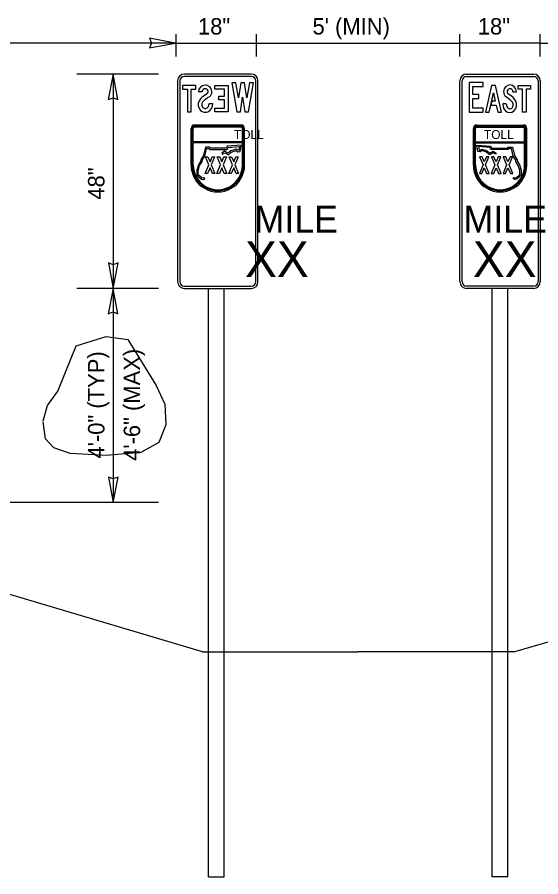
# Model space of a CAD drawing. Extents: x 56768 to 57406, y 11696 to 12105.
# Drawn here: x 56946.4 to 57035.7, y 11762.4 to 11908.9 of the extents above; entities that cross this region are included whole.
import ezdxf

# ---------------------------------------------------------------- set-up
doc = ezdxf.new("R2010")
doc.units = 0
for name, color, linetype in [('1', 7, 'Continuous'), ('52', 7, 'Continuous'), ('62', 7, 'Continuous'), ('DimLines_dp', 7, 'Continuous'), ('SignPanel', 7, 'Continuous'), ('XSGrdLine_ex', 7, 'Continuous')]:
    doc.layers.add(name, color=color, linetype=linetype)

msp = doc.modelspace()

# ---------------------------------------------------------------- linework, layer by layer
at = {"layer": '1'}
for p, q in [((56979.04, 11800.77), (56979.04, 11862.72)), ((56981.7, 11800.77), (56981.7, 11862.72)), ((57027.41, 11800.77), (57027.41, 11862.72)), ((57030.07, 11800.77), (57030.07, 11862.72)), ((56979.04, 11762.45), (56979.04, 11800.77)), ((56981.7, 11762.45), (56981.7, 11800.77)), ((57027.41, 11762.45), (57027.41, 11800.77)), ((57030.07, 11762.45), (57030.07, 11800.77)), ((56979.04, 11762.45), (56981.7, 11762.45)), ((57030.07, 11762.45), (57027.41, 11762.45))]:
    msp.add_line(p, q, dxfattribs=at)
at = {"layer": '52'}
msp.add_line((56970.53, 11826.22), (56892.41, 11826.22), dxfattribs=at)
at = {"layer": '62'}
msp.add_lwpolyline([(56950.87, 11840.16), (56951.57, 11842.76), (56953.37, 11845.17), (56956.48, 11852.92), (56961.58, 11854.52), (56965.28, 11854.02), (56970.08, 11846.17), (56971.58, 11842.96), (56971.78, 11839.46), (56970.58, 11836.46), (56967.48, 11834.75), (56961.58, 11834.25), (56955.47, 11834.55), (56952.67, 11835.56), (56951.27, 11837.06), (56950.87, 11839.96)], dxfattribs=at)
at = {"layer": 'DimLines_dp'}
for p, q in [((56973.53, 11902.22), (56973.53, 11906.05)), ((56987.21, 11902.22), (56987.21, 11906.05)), ((57021.89, 11902.22), (57021.89, 11906.05)), ((57035.58, 11902.22), (57035.58, 11906.05)), ((56973.53, 11904.5), (56892.41, 11904.5)), ((56973.34, 11904.5), (56968.99, 11905.34)), ((56968.99, 11905.34), (56969.32, 11904.5)), ((56969.32, 11904.5), (56968.99, 11903.69)), ((56968.99, 11903.69), (56973.34, 11904.5)), ((56973.53, 11904.5), (56987.21, 11904.5)), ((56987.21, 11904.5), (57021.89, 11904.5)), ((57035.58, 11904.5), (57021.89, 11904.5)), ((57035.58, 11904.5), (57116.7, 11904.5)), ((56970.53, 11899.22), (56956.6, 11899.22)), ((56962.78, 11899.22), (56961.94, 11894.87)), ((56962.78, 11899.22), (56962.78, 11862.72)), ((56963.59, 11894.87), (56962.78, 11899.22)), ((56961.94, 11894.87), (56962.78, 11895.2)), ((56962.78, 11895.2), (56963.59, 11894.87)), ((56962.78, 11866.74), (56961.97, 11867.07)), ((56961.97, 11867.07), (56962.78, 11862.72)), ((56962.78, 11866.74), (56961.97, 11867.07)), ((56961.97, 11867.07), (56962.78, 11862.72)), ((56962.78, 11862.72), (56963.62, 11867.07)), ((56963.62, 11867.07), (56962.78, 11866.74)), ((56962.78, 11862.72), (56963.62, 11867.07)), ((56963.62, 11867.07), (56962.78, 11866.74)), ((56970.53, 11862.72), (56956.6, 11862.72)), ((56962.78, 11862.72), (56961.94, 11858.37)), ((56962.78, 11862.72), (56962.78, 11826.22)), ((56963.59, 11858.37), (56962.78, 11862.72)), ((56961.94, 11858.37), (56962.78, 11858.7)), ((56962.78, 11858.7), (56963.59, 11858.37)), ((56962.78, 11830.24), (56961.97, 11830.57)), ((56961.97, 11830.57), (56962.78, 11826.22)), ((56962.78, 11826.22), (56963.62, 11830.57)), ((56963.62, 11830.57), (56962.78, 11830.24))]:
    msp.add_line(p, q, dxfattribs=at)
at = {"layer": 'SignPanel'}
for p, q in [((56977.92, 11896.21), (56977.31, 11896.21)), ((56977.92, 11896.21), (56977.31, 11896.21)), ((56977.92, 11896.21), (56977.31, 11896.21)), ((57030.93, 11896.21), (57031.52, 11896.21)), ((57030.93, 11896.21), (57031.52, 11896.21)), ((57030.93, 11896.21), (57031.52, 11896.21)), ((56979.12, 11894.2), (56979.74, 11894.2)), ((56979.12, 11894.2), (56979.74, 11894.2)), ((56979.12, 11894.2), (56979.74, 11894.2)), ((57029.79, 11894.17), (57029.2, 11894.17)), ((57029.79, 11894.17), (57029.2, 11894.17)), ((57029.79, 11894.17), (57029.2, 11894.17)), ((56976.05, 11883.7), (56976.05, 11889.98)), ((56976.25, 11883.7), (56976.25, 11889.98)), ((56976.44, 11887.7), (56976.44, 11889.98)), ((56984.61, 11890.55), (56976.62, 11890.55)), ((56984.61, 11890.36), (56976.62, 11890.36)), ((56984.61, 11890.17), (56976.62, 11890.17)), ((56984.8, 11887.7), (56984.8, 11889.98)), ((56984.99, 11883.7), (56984.99, 11889.98)), ((56985.18, 11883.7), (56985.18, 11889.98)), ((57024.18, 11883.7), (57024.18, 11889.98)), ((57024.37, 11883.7), (57024.37, 11889.98)), ((57024.55, 11887.7), (57024.55, 11889.98)), ((57024.75, 11890.55), (57032.73, 11890.55)), ((57024.75, 11890.36), (57032.73, 11890.36)), ((57024.75, 11890.17), (57032.73, 11890.17)), ((57032.92, 11887.7), (57032.92, 11889.98)), ((57033.11, 11883.7), (57033.11, 11889.98)), ((57033.3, 11883.7), (57033.3, 11889.98)), ((56984.8, 11887.7), (56976.44, 11887.7)), ((56976.44, 11883.7), (56976.44, 11887.51)), ((56984.8, 11887.51), (56976.44, 11887.51)), ((56978.5, 11886.77), (56978.17, 11885.34)), ((56979.24, 11886.77), (56978.5, 11886.77)), ((56979.34, 11886.62), (56979.24, 11886.77)), ((56982.07, 11886.62), (56979.34, 11886.62)), ((56982.21, 11886.96), (56982.07, 11886.62)), ((56984.59, 11887.14), (56982.21, 11886.96)), ((56982.23, 11886.39), (56982.37, 11886.74)), ((56982.37, 11886.74), (56984.31, 11886.89)), ((56983.33, 11886.8), (56983.33, 11886.8)), ((56984.31, 11886.89), (56984.22, 11886.26)), ((56984.42, 11886.05), (56984.59, 11887.14)), ((56984.8, 11883.7), (56984.8, 11887.51)), ((57024.55, 11887.7), (57032.92, 11887.7)), ((57024.55, 11883.7), (57024.55, 11887.51)), ((57024.55, 11887.51), (57032.92, 11887.51)), ((57024.94, 11886.05), (57024.77, 11887.14)), ((57024.77, 11887.14), (57027.15, 11886.96)), ((57026.99, 11886.74), (57025.04, 11886.89)), ((57025.04, 11886.89), (57025.14, 11886.26)), ((57026.03, 11886.8), (57026.03, 11886.8)), ((57027.13, 11886.39), (57026.99, 11886.74)), ((57027.15, 11886.96), (57027.28, 11886.62)), ((57027.28, 11886.62), (57030.01, 11886.62)), ((57030.01, 11886.62), (57030.12, 11886.77)), ((57030.12, 11886.77), (57030.85, 11886.77)), ((57030.85, 11886.77), (57031.18, 11885.34)), ((57032.92, 11883.7), (57032.92, 11887.51)), ((56978.17, 11885.34), (56977.72, 11884.61)), ((56977.95, 11884.54), (56978.39, 11885.25)), ((56978.39, 11885.25), (56978.69, 11886.54)), ((56978.69, 11886.54), (56979.12, 11886.54)), ((56979.12, 11886.54), (56979.22, 11886.39)), ((56979.22, 11886.39), (56982.23, 11886.39)), ((56981.78, 11886.09), (56981.28, 11885.75)), ((56981.28, 11885.75), (56981.41, 11885.56)), ((56981.41, 11885.56), (56981.79, 11885.82)), ((56982.39, 11885.73), (56981.78, 11886.09)), ((56981.79, 11885.82), (56982.42, 11885.45)), ((56982.84, 11886.15), (56982.39, 11885.73)), ((56982.42, 11885.45), (56982.96, 11885.95)), ((56983.76, 11886.45), (56982.84, 11886.15)), ((56982.96, 11885.95), (56983.71, 11886.19)), ((56983.71, 11886.19), (56983.96, 11886)), ((56984.03, 11886.24), (56983.76, 11886.45)), ((56983.96, 11886), (56984.42, 11886.05)), ((56984.22, 11886.26), (56984.03, 11886.24)), ((57025.39, 11886), (57024.94, 11886.05)), ((57025.14, 11886.26), (57025.33, 11886.24)), ((57025.33, 11886.24), (57025.6, 11886.45)), ((57025.64, 11886.19), (57025.39, 11886)), ((57025.6, 11886.45), (57026.52, 11886.15)), ((57026.4, 11885.95), (57025.64, 11886.19)), ((57026.94, 11885.45), (57026.4, 11885.95)), ((57026.52, 11886.15), (57026.97, 11885.73)), ((57027.57, 11885.82), (57026.94, 11885.45)), ((57026.97, 11885.73), (57027.58, 11886.09)), ((57030.14, 11886.39), (57027.13, 11886.39)), ((57027.95, 11885.56), (57027.57, 11885.82)), ((57027.58, 11886.09), (57028.08, 11885.75)), ((57028.08, 11885.75), (57027.95, 11885.56)), ((57030.24, 11886.54), (57030.14, 11886.39)), ((57030.67, 11886.54), (57030.24, 11886.54)), ((57030.97, 11885.25), (57030.67, 11886.54)), ((57031.41, 11884.54), (57030.97, 11885.25)), ((57031.18, 11885.34), (57031.64, 11884.61)), ((56977.31, 11883.75), (56977.06, 11882.83)), ((56977.29, 11882.8), (56977.52, 11883.66)), ((56977.72, 11884.43), (56977.31, 11883.75)), ((56977.52, 11883.66), (56977.95, 11884.36)), ((56977.72, 11884.61), (56977.72, 11884.43)), ((56977.95, 11884.36), (56977.95, 11884.54)), ((57031.41, 11884.36), (57031.41, 11884.54)), ((57031.83, 11883.66), (57031.41, 11884.36)), ((57031.64, 11884.61), (57031.64, 11884.43)), ((57031.64, 11884.43), (57032.05, 11883.75)), ((57032.07, 11882.8), (57031.83, 11883.66)), ((57032.05, 11883.75), (57032.3, 11882.83)), ((56977.06, 11882.83), (56977.06, 11881.97)), ((56977.29, 11882.07), (56977.29, 11882.8)), ((57032.07, 11882.07), (57032.07, 11882.8)), ((57032.3, 11882.83), (57032.3, 11881.97)), ((56977.06, 11881.97), (56977.81, 11881.35)), ((56977.91, 11881.56), (56977.29, 11882.07)), ((56977.81, 11881.35), (56978.17, 11881.26)), ((56978.12, 11881.51), (56977.91, 11881.56)), ((56978.26, 11881.61), (56978.12, 11881.51)), ((56978.17, 11881.26), (56978.39, 11881.42)), ((56978.39, 11881.42), (56978.26, 11881.61)), ((57030.96, 11881.42), (57031.09, 11881.61)), ((57031.19, 11881.26), (57030.96, 11881.42)), ((57031.09, 11881.61), (57031.24, 11881.51)), ((57031.55, 11881.35), (57031.19, 11881.26)), ((57031.24, 11881.51), (57031.44, 11881.56)), ((57031.44, 11881.56), (57032.07, 11882.07)), ((57032.3, 11881.97), (57031.55, 11881.35))]:
    msp.add_line(p, q, dxfattribs=at)
for points in [[(56986.32, 11899.22), (56974.91, 11899.22)], [(56986.32, 11898.84), (56974.91, 11898.84)], [(57023.03, 11899.22), (57034.44, 11899.22)], [(57023.03, 11898.84), (57034.44, 11898.84)], [(56973.77, 11898.08), (56973.77, 11863.86)], [(56974.15, 11898.08), (56974.15, 11863.86)], [(56987.08, 11863.86), (56987.08, 11898.08)], [(56987.46, 11863.86), (56987.46, 11898.08)], [(57021.89, 11863.86), (57021.89, 11898.08)], [(57022.27, 11863.86), (57022.27, 11898.08)], [(57035.2, 11898.08), (57035.2, 11863.86)], [(57035.58, 11898.08), (57035.58, 11863.86)], [(56974.91, 11863.1), (56986.32, 11863.1)], [(56974.91, 11862.72), (56986.32, 11862.72)], [(57034.44, 11863.1), (57023.03, 11863.1)], [(57034.44, 11862.72), (57023.03, 11862.72)]]:
    msp.add_lwpolyline(points, dxfattribs=at)
for points in [[(56976.06, 11896.66), (56976.88, 11896.66), (56976.88, 11897.29), (56974.62, 11897.29), (56974.62, 11896.66), (56975.44, 11896.66), (56975.44, 11892.79), (56976.06, 11892.79)], [(56976.06, 11896.66), (56976.88, 11896.66), (56976.88, 11897.29), (56974.62, 11897.29), (56974.62, 11896.66), (56975.44, 11896.66), (56975.44, 11892.79), (56976.06, 11892.79)], [(56976.06, 11896.66), (56976.88, 11896.66), (56976.88, 11897.29), (56974.62, 11897.29), (56974.62, 11896.66), (56975.44, 11896.66), (56975.44, 11892.79), (56976.06, 11892.79)], [(56981.77, 11893.42), (56981.77, 11894.86), (56980.8, 11894.86), (56980.8, 11895.49), (56981.77, 11895.49), (56981.77, 11896.66), (56980.13, 11896.66), (56980.13, 11897.29), (56982.39, 11897.29), (56982.39, 11892.79), (56980.13, 11892.79), (56980.13, 11893.42)], [(56981.77, 11893.42), (56981.77, 11894.86), (56980.8, 11894.86), (56980.8, 11895.49), (56981.77, 11895.49), (56981.77, 11896.66), (56980.13, 11896.66), (56980.13, 11897.29), (56982.39, 11897.29), (56982.39, 11892.79), (56980.13, 11892.79), (56980.13, 11893.42)], [(56981.77, 11893.42), (56981.77, 11894.86), (56980.8, 11894.86), (56980.8, 11895.49), (56981.77, 11895.49), (56981.77, 11896.66), (56980.13, 11896.66), (56980.13, 11897.29), (56982.39, 11897.29), (56982.39, 11892.79), (56980.13, 11892.79), (56980.13, 11893.42)], [(56985.55, 11895.18), (56985.15, 11897.74), (56984.55, 11897.74), (56984.14, 11895.18), (56983.69, 11897.74), (56982.99, 11897.74), (56983.87, 11892.79), (56984.46, 11892.79), (56984.85, 11895.27), (56985.24, 11892.79), (56985.82, 11892.79), (56986.7, 11897.74), (56986.01, 11897.74)], [(56985.55, 11895.18), (56985.15, 11897.74), (56984.55, 11897.74), (56984.14, 11895.18), (56983.69, 11897.74), (56982.99, 11897.74), (56983.87, 11892.79), (56984.46, 11892.79), (56984.85, 11895.27), (56985.24, 11892.79), (56985.82, 11892.79), (56986.7, 11897.74), (56986.01, 11897.74)], [(56985.55, 11895.18), (56985.15, 11897.74), (56984.55, 11897.74), (56984.14, 11895.18), (56983.69, 11897.74), (56982.99, 11897.74), (56983.87, 11892.79), (56984.46, 11892.79), (56984.85, 11895.27), (56985.24, 11892.79), (56985.82, 11892.79), (56986.7, 11897.74), (56986.01, 11897.74)], [(57024.1, 11893.44), (57024.1, 11895.07), (57025.12, 11895.07), (57025.12, 11895.77), (57024.1, 11895.77), (57024.1, 11897.09), (57025.82, 11897.09), (57025.82, 11897.8), (57023.45, 11897.8), (57023.45, 11892.74), (57025.82, 11892.74), (57025.82, 11893.44)], [(57024.1, 11893.44), (57024.1, 11895.07), (57025.12, 11895.07), (57025.12, 11895.77), (57024.1, 11895.77), (57024.1, 11897.09), (57025.82, 11897.09), (57025.82, 11897.8), (57023.45, 11897.8), (57023.45, 11892.74), (57025.82, 11892.74), (57025.82, 11893.44)], [(57024.1, 11893.44), (57024.1, 11895.07), (57025.12, 11895.07), (57025.12, 11895.77), (57024.1, 11895.77), (57024.1, 11897.09), (57025.82, 11897.09), (57025.82, 11897.8), (57023.45, 11897.8), (57023.45, 11892.74), (57025.82, 11892.74), (57025.82, 11893.44)], [(57028.07, 11893.96), (57028.34, 11892.74), (57028.95, 11892.74), (57027.93, 11897.31), (57027.29, 11897.31), (57026.27, 11892.74), (57026.88, 11892.74), (57027.15, 11893.96)], [(57027.3, 11894.6), (57027.15, 11893.96), (57028.07, 11893.96), (57028.34, 11892.74), (57028.95, 11892.74), (57027.93, 11897.31), (57027.29, 11897.31), (57026.27, 11892.74), (57026.88, 11892.74), (57027.61, 11896.01), (57027.92, 11894.6)], [(57027.3, 11894.6), (57027.15, 11893.96), (57028.07, 11893.96), (57028.34, 11892.74), (57028.95, 11892.74), (57027.93, 11897.31), (57027.29, 11897.31), (57026.27, 11892.74), (57026.88, 11892.74), (57027.61, 11896.01), (57027.92, 11894.6)], [(57032.58, 11896.67), (57031.8, 11896.67), (57031.8, 11897.31), (57033.94, 11897.31), (57033.94, 11896.67), (57033.16, 11896.67), (57033.16, 11892.74), (57032.58, 11892.74)], [(57032.58, 11896.67), (57031.8, 11896.67), (57031.8, 11897.31), (57033.94, 11897.31), (57033.94, 11896.67), (57033.16, 11896.67), (57033.16, 11892.74), (57032.58, 11892.74)], [(57032.58, 11896.67), (57031.8, 11896.67), (57031.8, 11897.31), (57033.94, 11897.31), (57033.94, 11896.67), (57033.16, 11896.67), (57033.16, 11892.74), (57032.58, 11892.74)], [(57027.61, 11896.01), (57027.92, 11894.6), (57027.3, 11894.6)], [(56979.7, 11882.29), (56979.29, 11883.26), (56978.88, 11882.29), (56978.45, 11882.29), (56979.07, 11883.77), (56978.5, 11885.14), (56978.93, 11885.14), (56979.29, 11884.28), (56979.65, 11885.14), (56980.07, 11885.14), (56979.5, 11883.77), (56980.12, 11882.29)], [(56981.71, 11882.29), (56981.3, 11883.26), (56980.9, 11882.29), (56980.47, 11882.29), (56981.09, 11883.77), (56980.52, 11885.14), (56980.95, 11885.14), (56981.3, 11884.28), (56981.66, 11885.14), (56982.09, 11885.14), (56981.52, 11883.77), (56982.14, 11882.29)], [(56983.73, 11882.29), (56983.32, 11883.26), (56982.91, 11882.29), (56982.48, 11882.29), (56983.11, 11883.77), (56982.53, 11885.14), (56982.96, 11885.14), (56983.32, 11884.28), (56983.68, 11885.14), (56984.11, 11885.14), (56983.53, 11883.77), (56984.16, 11882.29)], [(57025.63, 11882.29), (57026.04, 11883.26), (57026.44, 11882.29), (57026.87, 11882.29), (57026.25, 11883.77), (57026.82, 11885.14), (57026.39, 11885.14), (57026.04, 11884.28), (57025.68, 11885.14), (57025.25, 11885.14), (57025.82, 11883.77), (57025.2, 11882.29)], [(57027.64, 11882.29), (57028.05, 11883.26), (57028.46, 11882.29), (57028.89, 11882.29), (57028.27, 11883.77), (57028.84, 11885.14), (57028.41, 11885.14), (57028.05, 11884.28), (57027.69, 11885.14), (57027.27, 11885.14), (57027.84, 11883.77), (57027.22, 11882.29)], [(57029.66, 11882.29), (57030.07, 11883.26), (57030.48, 11882.29), (57030.9, 11882.29), (57030.28, 11883.77), (57030.85, 11885.14), (57030.43, 11885.14), (57030.07, 11884.28), (57029.71, 11885.14), (57029.28, 11885.14), (57029.85, 11883.77), (57029.23, 11882.29)]]:
    msp.add_lwpolyline(points, close=True, dxfattribs=at)
for centre, radius, start, end in [((56974.91, 11898.08), 1.14, 90, 180), ((56974.91, 11898.08), 0.76, 90, 180), ((56986.32, 11898.08), 1.14, 0, 90), ((56986.32, 11898.08), 0.76, 0, 90), ((57023.03, 11898.08), 1.14, 90, 180), ((57023.03, 11898.08), 0.76, 90, 180), ((57034.44, 11898.08), 1.14, 0, 90), ((57034.44, 11898.08), 0.76, 0, 90), ((56974.91, 11863.86), 1.14, 180, 270), ((56974.91, 11863.86), 0.76, 180, 270), ((56986.32, 11863.86), 1.14, 270, 0), ((56986.32, 11863.86), 0.76, 270, 0), ((57023.03, 11863.86), 1.14, 180, 270), ((57023.03, 11863.86), 0.76, 180, 270), ((57034.44, 11863.86), 1.14, 270, 360), ((57034.44, 11863.86), 0.76, 270, 360)]:
    msp.add_arc(centre, radius, start, end, dxfattribs=at)
for centre, major_axis, ratio, start_param, end_param in [((56978.46, 11896.18), (0, -1.17), 0.981197, 1.634182, 4.688511), ((56978.46, 11896.18), (0, -1.17), 0.981197, 1.634182, 4.688511), ((56978.46, 11896.18), (0, -1.17), 0.981197, 1.634182, 4.688511), ((57030.42, 11896.18), (0, 1.19), 0.91923, 4.736267, 7.790596), ((57030.42, 11896.18), (0, 1.19), 0.91923, 4.736267, 7.790596), ((57030.42, 11896.18), (0, 1.19), 0.91923, 4.736267, 7.790596), ((56980.77, 11892.05), (0, -4.32), 0.981197, 3.642536, 3.961892), ((56980.77, 11892.05), (0, -4.32), 0.981197, 3.642536, 3.961892), ((56980.77, 11892.05), (0, -4.32), 0.981197, 3.642536, 3.961892), ((56978.46, 11896.17), (0, -0.55), 0.981197, 2.28404, 4.637874), ((56978.46, 11896.17), (0, -0.55), 0.981197, 2.28404, 4.637874), ((56978.46, 11896.17), (0, -0.55), 0.981197, 2.28404, 4.637874), ((56981.31, 11891.36), (0, -4.56), 0.981197, 3.63779, 3.909641), ((56981.31, 11891.36), (0, -4.56), 0.981197, 3.63779, 3.909641), ((56981.31, 11891.36), (0, -4.56), 0.981197, 3.63779, 3.909641), ((56978.53, 11896.24), (0, -0.453), 0.981197, 0.484634, 2.267813), ((56978.53, 11896.24), (0, -0.453), 0.981197, 0.484634, 2.267813), ((56978.53, 11896.24), (0, -0.453), 0.981197, 0.484634, 2.267813), ((56978.57, 11896.22), (0, -1.05), 0.981197, 0.629826, 1.606762), ((56978.57, 11896.22), (0, -1.05), 0.981197, 0.629826, 1.606762), ((56978.57, 11896.22), (0, -1.05), 0.981197, 0.629826, 1.606762), ((57030.31, 11896.22), (0, 1.07), 0.91923, 1.534831, 2.511766), ((57030.31, 11896.22), (0, 1.07), 0.91923, 1.534831, 2.511766), ((57030.31, 11896.22), (0, 1.07), 0.91923, 1.534831, 2.511766), ((57027.71, 11891.28), (0, 4.63), 0.91923, 5.515137, 5.786988), ((57027.71, 11891.28), (0, 4.63), 0.91923, 5.515137, 5.786988), ((57027.71, 11891.28), (0, 4.63), 0.91923, 5.515137, 5.786988), ((57030.35, 11896.24), (0, 0.46), 0.91923, 0.87378, 2.656959), ((57030.35, 11896.24), (0, 0.46), 0.91923, 0.87378, 2.656959), ((57030.35, 11896.24), (0, 0.46), 0.91923, 0.87378, 2.656959), ((57030.42, 11896.17), (0, 0.558), 0.91923, 4.786904, 7.140738), ((57030.42, 11896.17), (0, 0.558), 0.91923, 4.786904, 7.140738), ((57030.42, 11896.17), (0, 0.558), 0.91923, 4.786904, 7.140738), ((57028.22, 11891.98), (0, 4.39), 0.91923, 5.462886, 5.782242), ((57028.22, 11891.98), (0, 4.39), 0.91923, 5.462886, 5.782242), ((57028.22, 11891.98), (0, 4.39), 0.91923, 5.462886, 5.782242), ((56978.65, 11894.02), (0, -1.4), 0.981197, 3.939023, 5.163791), ((56978.65, 11894.02), (0, -1.4), 0.981197, 3.939023, 5.163791), ((56978.65, 11894.02), (0, -1.4), 0.981197, 3.939023, 5.163791), ((56978.66, 11894.02), (0, -0.78), 0.981197, 3.79238, 5.170369), ((56978.66, 11894.02), (0, -0.78), 0.981197, 3.79238, 5.170369), ((56978.66, 11894.02), (0, -0.78), 0.981197, 3.79238, 5.170369), ((56978.24, 11894.16), (0, -0.897), 0.981197, 0.859453, 1.616836), ((56978.3, 11894.14), (0, -1.47), 0.981197, 0.439911, 1.615229), ((56978.24, 11894.16), (0, -0.897), 0.981197, 0.859453, 1.616836), ((56978.3, 11894.14), (0, -1.47), 0.981197, 0.439911, 1.615229), ((56978.24, 11894.16), (0, -0.897), 0.981197, 0.859453, 1.616836), ((56978.3, 11894.14), (0, -1.47), 0.981197, 0.439911, 1.615229), ((57030.57, 11894.1), (0, 1.5), 0.91923, 1.526364, 2.701682), ((57030.57, 11894.1), (0, 1.5), 0.91923, 1.526364, 2.701682), ((57030.57, 11894.1), (0, 1.5), 0.91923, 1.526364, 2.701682), ((57030.63, 11894.13), (0, 0.911), 0.91923, 1.524757, 2.28214), ((57030.63, 11894.13), (0, 0.911), 0.91923, 1.524757, 2.28214), ((57030.63, 11894.13), (0, 0.911), 0.91923, 1.524757, 2.28214), ((57030.23, 11893.99), (0, 0.792), 0.91923, 4.254409, 5.632398), ((57030.23, 11893.99), (0, 0.792), 0.91923, 4.254409, 5.632398), ((57030.23, 11893.99), (0, 0.792), 0.91923, 4.254409, 5.632398), ((57030.24, 11893.98), (0, 1.42), 0.91923, 4.260987, 5.485755), ((57030.24, 11893.98), (0, 1.42), 0.91923, 4.260987, 5.485755), ((57030.24, 11893.98), (0, 1.42), 0.91923, 4.260987, 5.485755), ((56978.5, 11893.95), (0, -1.23), 0.981197, 5.173086, 6.638731), ((56978.5, 11893.95), (0, -1.23), 0.981197, 5.173086, 6.638731), ((56978.5, 11893.95), (0, -1.23), 0.981197, 5.173086, 6.638731), ((56978.47, 11893.94), (0, -0.572), 0.981197, 5.194718, 7.162991), ((56978.47, 11893.94), (0, -0.572), 0.981197, 5.194718, 7.162991), ((56978.47, 11893.94), (0, -0.572), 0.981197, 5.194718, 7.162991), ((57030.39, 11893.92), (0, 1.24), 0.91923, 2.786047, 4.251692), ((57030.39, 11893.92), (0, 1.24), 0.91923, 2.786047, 4.251692), ((57030.39, 11893.92), (0, 1.24), 0.91923, 2.786047, 4.251692), ((57030.41, 11893.9), (0, 0.581), 0.91923, 2.261787, 4.23006), ((57030.41, 11893.9), (0, 0.581), 0.91923, 2.261787, 4.23006), ((57030.41, 11893.9), (0, 0.581), 0.91923, 2.261787, 4.23006), ((56976.63, 11889.98), (0, 0.57), 0.9997, 0, 1.570796), ((56976.63, 11889.98), (0, 0.38), 0.9997, 0, 1.570796), ((56976.63, 11889.98), (0, 0.19), 0.9997, 0, 1.570796), ((56984.61, 11889.98), (0, 0.57), 0.9997, 4.712389, 6.283185), ((56984.61, 11889.98), (0, 0.38), 0.9997, 4.712389, 6.283185), ((56984.61, 11889.98), (0, 0.19), 0.9997, 4.712389, 6.283185), ((57024.75, 11889.98), (0, 0.57), 0.9997, 0, 1.570796), ((57024.75, 11889.98), (0, 0.38), 0.9997, 0, 1.570796), ((57024.75, 11889.98), (0, 0.19), 0.9997, 0, 1.570796), ((57032.73, 11889.98), (0, 0.57), 0.9997, 4.712389, 6.283185), ((57032.73, 11889.98), (0, 0.38), 0.9997, 4.712389, 6.283185), ((57032.73, 11889.98), (0, 0.19), 0.9997, 4.712389, 6.283185), ((56980.62, 11883.71), (0, 4.56), 0.9997, 1.570796, 4.712389), ((56980.62, 11883.71), (0, 4.37), 0.9997, 1.570796, 4.712389), ((56980.62, 11883.71), (0, 4.18), 0.9997, 1.570796, 4.712389), ((57028.74, 11883.71), (0, -4.56), 0.9997, 4.712389, 7.853982), ((57028.74, 11883.71), (0, -4.37), 0.9997, 4.712389, 7.853982), ((57028.74, 11883.71), (0, -4.18), 0.9997, 4.712389, 7.853982)]:
    msp.add_ellipse(centre, major_axis=major_axis, ratio=ratio, start_param=start_param, end_param=end_param, dxfattribs=at)
at = {"layer": 'XSGrdLine_ex'}
for p, q in [((56978.01, 11800.77), (56913.04, 11820.09)), ((57031.1, 11800.77), (57096.06, 11820.09)), ((56978.01, 11800.77), (57004.55, 11800.77)), ((57031.1, 11800.77), (57004.55, 11800.77))]:
    msp.add_line(p, q, dxfattribs=at)

# ---------------------------------------------------------------- texts
at = {"layer": 'DimLines_dp'}
for s, p in [('18"', (56977.23, 11905.97)), ("5' (MIN)", (56996.76, 11905.97)), ('18"', (57024.93, 11905.97))]:
    msp.add_text(s, height=2.8, dxfattribs=at).set_placement(p)
for s, p in [('48"', (56961.29, 11877.83)), ('4\'-0" (TYP)', (56961.29, 11833.72)), ('4\'-6" (MAX)', (56967.37, 11833.32))]:
    msp.add_text(s, height=2.8, rotation=90, dxfattribs=at).set_placement(p)
at = {"layer": 'SignPanel'}
for s, height, p in [('TOLL', 1.519, (56983.37, 11888.17)), ('TOLL', 1.519, (57025.98, 11888.17)), ('MILE', 4.562, (56986.87, 11872.22)), ('MILE', 4.562, (57022.48, 11872.22)), ('XX', 6.083, (56985.26, 11864.65)), ('XX', 6.083, (57024.09, 11864.65))]:
    msp.add_text(s, height=height, dxfattribs=at).set_placement(p)

doc.saveas('drawing.dxf')
